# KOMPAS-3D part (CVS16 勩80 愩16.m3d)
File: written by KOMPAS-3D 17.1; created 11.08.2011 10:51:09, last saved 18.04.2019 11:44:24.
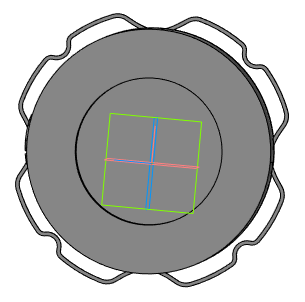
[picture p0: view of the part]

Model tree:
1. Плоскость XY
2. Плоскость ZX
3. Плоскость ZY
4. Ось X
5. Ось Y
6. Ось Z
7. Начало координат
8. Операция без истории:2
